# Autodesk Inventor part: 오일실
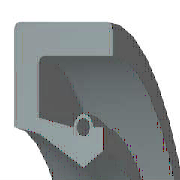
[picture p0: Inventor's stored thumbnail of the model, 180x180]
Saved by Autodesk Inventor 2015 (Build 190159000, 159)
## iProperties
IsCustomPart: 1
Created: 2015-10
Part Number: 오일실
Material: Rubber
Description: 오일-실
Document SubType Name: Modeling
Standard: KS B 2804
Designer: mdu
Standards Organization: KS
Language: ko-KR
Size Designation: S - 25 38 8
Categories: <MemberInstance><Categories><Category DisplayName="샤프트 부품" InternalName="7f7aeb1f-a693-4053-b835-cee3144e0d98" Mnemonic="SHFT"><Category DisplayName="실링" Intern
Density: 0.93 g/cm^3
Mass: 2.23721 g
Surface Area: 37.0166 cm^2
Volume: 2.4056 cm^3
Appearance: Rubber - Black - Version 1.1
Author: mdu
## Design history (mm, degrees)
revolve "본체" stored, may be unused: angle "d17" = 90 deg
revolve "스프링1" stored, may be unused: angle "d18" = 90 deg
body "Solid1"
sketch "스케치1"
  geometry: L1 (0, 19)-(8, 19); L2 (8, 19)-(8, 17.75); L3 (8, 17.75)-(1.75, 17.75); L4 (0, 19)-(0, 14.6); L5 (0, 14.6)-(1.75, 14.25); L6 (1.75, 14.25)-(4.9, 12.5); L7 (4.9, 12.5)-(0, 12.5); L8 (6.3, 13.375)-(6.3, 14.6); L9 (0, 0)-(9.586, 0) reference; L10 (4.9, 12.5)-(6.3, 13.375); L11 (0, 18)-(0, -3) reference; L12 (-1.917, 0)-(11.503, 0) reference; L13 (4.2, 14.6)-(1.75, 15.09); L14 (1.75, 15.09)-(1.75, 17.75); L15 (6.3, 14.6)-(5.6, 14.6); C1 r 0.455 at (4.9, 14.6); A1 r 0.7 centre (4.9, 14.6) between (5.6, 14.6) and (4.2, 14.6)
  constraints: 26 end point, 5 horizontal alignment, 4 perpendicular, 2 centre point, 2 collinear, 2 horizontal, 2 parallel, 2 point on circle, 2 point on line, 2 vertical alignment, 1 coincident
  dimensions: "d0" = 38 diameter of L1 L9 (= SD2); "d1" = 26.75 diameter of L8.start L9 (= ABDM); "d2" = 1.25 distance of L1.end L2.end (computed from SD); "d3" = 0.91 diameter of C1 (= SPDI); "d4" = 1.4 diameter of A1 (= SPDA); "d5" = 25 diameter of L6.end L9 (= NND); "d6" = 28.5 diameter of L5.end L9 (= TKDM); "d7" = 29.2 diameter of L4.end L9 (= HLDM); "d8" = 4.9 distance from line of C1.centre L4 (= SPDST); "d9" = 6.3 distance between parallel lines of L8 L4 (= SDI); "d10" = 8 distance between parallel lines of L2 L4 (= SWDT); "d12" = 1.75 distance between parallel lines of L14 L4 (= SD)
fillet "모깎기1" dims "d11" = 0.3 (= RR)
other parameters: "SD2" = 38 [user parameter; used in 1 equation term], "SWDT" = 8 [user parameter; used in 1 equation term], "RR" = 0.3 [user parameter; used in 1 equation term], "SD" = 1.75 [user parameter; used in 2 equation terms], "NND" = 25 [user parameter; used in 1 equation term], "SPDA" = 1.4 [user parameter; used in 1 equation term], "SPDI" = 0.91 [user parameter; used in 1 equation term], "TKDM" = 28.5 [user parameter; used in 1 equation term], "HLDM" = 29.2 [user parameter; used in 1 equation term], "ABDM" = 26.75 [user parameter; used in 1 equation term], "SDI" = 6.3 [user parameter; used in 1 equation term], "SPDST" = 4.9 [user parameter; used in 1 equation term], "d13" = 0, "d14" = 0, "d15" = 0, "LAB" = 0.35 [user parameter]
